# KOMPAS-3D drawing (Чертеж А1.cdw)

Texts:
  Проект двухэтажного  административного здания
  Wik
  Принципиальная схема здания
  Армирование перекрытия второго этажа
  Схема армирования плиты П1
  Схема армирования балки Б1
  Схема армирования балки
  Схема армирования 1 м погонного плиты в пролете
  Колонна
  Фундамент под колонну
  Кол1
  Второй этаж
  Армирование перекрытия первого этажа
  Арматура колонны условно не показана
  Проект двухэтажного
  административного здания
Dimensions and other numbers on the sheet: 1; 2; 3; 4; 5; 1:100; 1:40; 1:50; 2-2; 1:10; 6800; 5300; 400; 200; 1-1; 1450; 9х150; 50; 17х300; 100; 150; 15; 1:20; 20; 130; 7х325=2275; 2262,5; 325; 11х200=2200; 62,5; 300; 25; 15х350=5250; 35; 155х6=930; 5х190=950; 1325; 350х8=2800; 75; 10х200=2000; 7х350=2450; 30; 170; 1400; 7х190=1330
